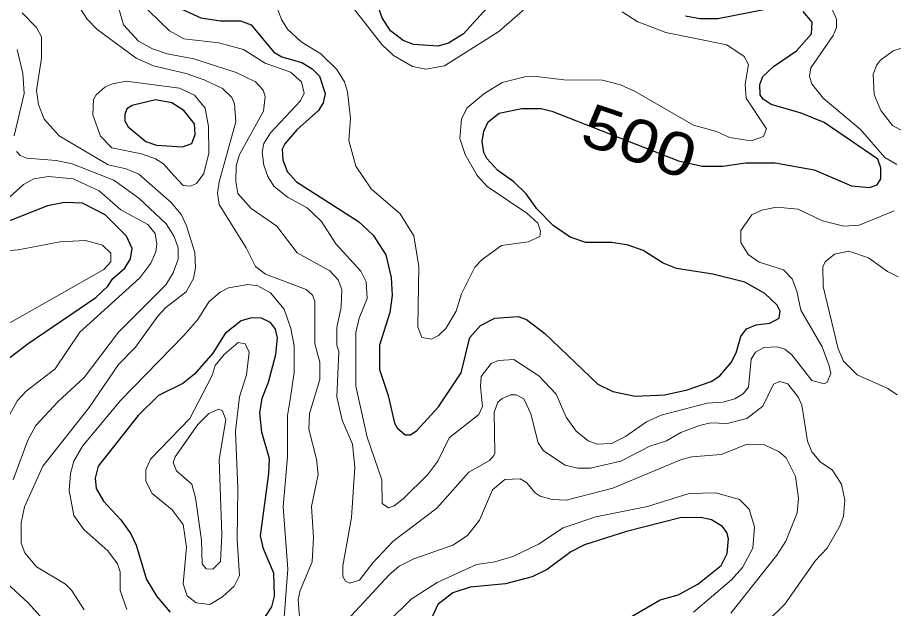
# Model space of a CAD drawing. Extents: x 577 to 602.9, y 7483.8 to 7511.6.
# Drawn here: x 595.926 to 597.557, y 7484.927 to 7486.028 of the extents above; entities that cross this region are included whole.
import ezdxf
from ezdxf.enums import TextEntityAlignment as Align

# ---------------------------------------------------------------- set-up
doc = ezdxf.new("R2010")
doc.units = 0
doc.header["$LTSCALE"] = 0.032
doc.layers.add('1', color=7, linetype='Continuous', lineweight=25)
doc.layers.add('2', color=7, linetype='Continuous', lineweight=13)
doc.layers.add('61', color=7, linetype='Continuous')

msp = doc.modelspace()

# ---------------------------------------------------------------- linework, layer by layer
at = {"layer": '1'}
for points in [[(596.8685, 7486.1208), (596.7564, 7485.9975), (596.7286, 7485.98), (596.7095, 7485.9745), (596.6634, 7485.9776), (596.6443, 7485.9848), (596.6204, 7486.0031), (596.6053, 7486.0269), (596.5703, 7486.1263)], [(596.2324, 7486.0436), (596.2674, 7486.0269), (596.3039, 7486.0214), (596.3413, 7486.0214), (596.3612, 7486.0142), (596.4033, 7485.9633), (596.4185, 7485.9546), (596.4558, 7485.9442), (596.4749, 7485.9323), (596.4884, 7485.9188), (596.4988, 7485.8862), (596.4956, 7485.8687), (596.4868, 7485.8544), (596.4463, 7485.8186), (596.424, 7485.7924), (596.4192, 7485.7828), (596.42, 7485.7629), (596.428, 7485.7407), (596.4455, 7485.7216), (596.5608, 7485.6476), (596.5886, 7485.6222), (596.6117, 7485.5856), (596.622, 7485.5435), (596.6236, 7485.5101), (596.6196, 7485.4783), (596.6005, 7485.4178), (596.6005, 7485.3725), (596.6165, 7485.324), (596.6284, 7485.2723), (596.6332, 7485.2636), (596.6483, 7485.2508), (596.6578, 7485.2508), (596.6697, 7485.2588), (596.7103, 7485.3025), (596.7524, 7485.3662), (596.7683, 7485.4321), (596.7882, 7485.4544), (596.8152, 7485.4679), (596.8582, 7485.4711), (596.8741, 7485.4655), (596.9083, 7485.4393), (597.0069, 7485.3447), (597.0347, 7485.3312), (597.0761, 7485.3224)], [(597.0761, 7485.3224), (597.1317, 7485.3248), (597.1731, 7485.3343), (597.2176, 7485.3502), (597.2343, 7485.3606), (597.255, 7485.3852), (597.2645, 7485.4035), (597.2733, 7485.4337), (597.2836, 7485.4481), (597.3019, 7485.4552), (597.3273, 7485.4584), (597.3448, 7485.4679), (597.3464, 7485.4807), (597.3409, 7485.4918), (597.3178, 7485.5141), (597.2804, 7485.5347), (597.2208, 7485.5498), (597.1532, 7485.5602), (597.1285, 7485.5705), (597.0912, 7485.5936), (597.0633, 7485.6039), (597.0331, 7485.6087), (596.9846, 7485.6087), (596.9552, 7485.619), (596.9234, 7485.6405), (596.8932, 7485.6715), (596.8733, 7485.6993), (596.8502, 7485.7216), (596.8208, 7485.7431), (596.8001, 7485.7653), (596.7946, 7485.7765), (596.7914, 7485.7971), (596.7946, 7485.8162), (596.8025, 7485.8337), (596.8232, 7485.8496), (596.8653, 7485.8584), (596.9011, 7485.8584), (596.921, 7485.8536), (597.1572, 7485.7606), (597.2009, 7485.751), (597.2399, 7485.751), (597.282, 7485.7574), (597.3369, 7485.7574), (597.41, 7485.7439), (597.4792, 7485.7144), (597.5126, 7485.7113), (597.5269, 7485.716), (597.5341, 7485.7272), (597.5341, 7485.7478), (597.5285, 7485.7637), (597.4283, 7485.8321), (597.3854, 7485.8496), (597.3297, 7485.8655), (597.3146, 7485.8759), (597.3091, 7485.8838), (597.3083, 7485.9029), (597.3138, 7485.918), (597.3337, 7485.9363), (597.3766, 7485.9657), (597.4045, 7485.9975), (597.4061, 7486.019), (597.3894, 7486.0389)], [(597.3417, 7486.0468), (597.2303, 7486.0254), (597.1969, 7486.0254), (597.1699, 7486.0301)], [(595.904, 7485.3884), (595.9461, 7485.421), (596.0718, 7485.5061), (596.094, 7485.5276), (596.1036, 7485.5419), (596.1258, 7485.561), (596.1362, 7485.5785), (596.1393, 7485.5975), (596.129, 7485.6206), (596.0893, 7485.6604), (596.0471, 7485.6818), (596.0137, 7485.6834), (595.9819, 7485.6771), (595.9016, 7485.6453)], [(596.3866, 7484.9105), (596.3994, 7484.9304), (596.4049, 7484.9503), (596.4033, 7484.9932), (596.3843, 7485.0385), (596.3787, 7485.0624), (596.394, 7485.1784), (596.3953, 7485.2062), (596.3811, 7485.2556), (596.3771, 7485.2914), (596.3819, 7485.3192), (596.3938, 7485.3487), (596.4073, 7485.4003), (596.4105, 7485.4314), (596.4065, 7485.4473), (596.397, 7485.46), (596.3803, 7485.4679), (596.362, 7485.4687), (596.3429, 7485.4632), (596.3127, 7485.4393), (596.2896, 7485.4027), (596.2554, 7485.3638), (596.234, 7485.3463), (596.1886, 7485.324), (596.1505, 7485.2866), (596.0765, 7485.192), (596.071, 7485.1697), (596.0726, 7485.1507), (596.0861, 7485.1268), (596.1187, 7485.0926), (596.137, 7485.0664), (596.1473, 7485.0449), (596.1664, 7484.9813), (596.1855, 7484.9495), (596.2101, 7484.9201)], [(597.0172, 7484.8819), (597.123, 7484.9431), (597.1564, 7484.9527), (597.193, 7484.9725), (597.2367, 7485.0075), (597.2478, 7485.0298), (597.2502, 7485.0568), (597.247, 7485.0688), (597.2391, 7485.0799), (597.2184, 7485.0926), (597.1985, 7485.0966), (597.1604, 7485.0958), (597.0602, 7485.0703), (596.9822, 7485.0457), (596.9568, 7485.033), (596.9123, 7484.9996), (596.8844, 7484.9861), (596.8351, 7484.9733), (596.7691, 7484.967), (596.7365, 7484.9566), (596.7087, 7484.9344), (596.688, 7484.889)]]:
    msp.add_lwpolyline(points, dxfattribs=at)
msp.add_lwpolyline([(596.2356, 7485.8544), (596.2133, 7485.8687), (596.1831, 7485.8743), (596.1393, 7485.8639), (596.1298, 7485.8576), (596.1258, 7485.8472), (596.1258, 7485.8353), (596.1322, 7485.8242), (596.1648, 7485.7971), (596.1847, 7485.79), (596.2332, 7485.7868), (596.2507, 7485.7932), (596.257, 7485.8099), (596.2554, 7485.8297)], close=True, dxfattribs=at)
at = {"layer": '2'}
for points in [[(596.5401, 7486.0603), (596.6045, 7485.9776), (596.626, 7485.957), (596.6618, 7485.9363), (596.6864, 7485.9315), (596.7214, 7485.9379), (596.8224, 7486.0015), (596.9202, 7486.0874)], [(597.5635, 7485.7542), (597.5412, 7485.7669), (597.4959, 7485.8194), (597.4267, 7485.8774), (597.4053, 7485.9045), (597.4013, 7485.918), (597.4037, 7485.9339), (597.445, 7485.9943), (597.4514, 7486.0094), (597.4514, 7486.0246), (597.4418, 7486.046), (597.4259, 7486.0675), (597.4124, 7486.0794), (597.383, 7486.089), (597.3377, 7486.0882), (597.2327, 7486.0731), (597.2009, 7486.0731), (597.1635, 7486.0794)], [(596.1075, 7486.0715), (596.1234, 7486.0142), (596.1513, 7485.984), (596.1775, 7485.9697), (596.2046, 7485.9601), (596.2546, 7485.9506), (596.3334, 7485.9252), (596.3692, 7485.9077), (596.3835, 7485.8926), (596.3874, 7485.8806), (596.3843, 7485.8536), (596.3397, 7485.7725), (596.3334, 7485.7518), (596.3326, 7485.7224), (596.3366, 7485.7001), (596.3612, 7485.6723), (596.4089, 7485.6389), (596.4471, 7485.5896), (596.5075, 7485.5562), (596.5234, 7485.5395), (596.5298, 7485.5212), (596.529, 7485.4886), (596.521, 7485.4504), (596.521, 7485.4178), (596.5242, 7485.4059), (596.521, 7485.3216), (596.5306, 7485.2779), (596.5497, 7485.2334), (596.5544, 7485.1904), (596.5481, 7485.0966), (596.5322, 7485.0067), (596.5322, 7484.9869), (596.5369, 7484.9781), (596.5449, 7484.9741), (596.5632, 7484.9797), (596.5878, 7485.0123), (596.6252, 7485.0521)], [(596.1521, 7486.058), (596.2093, 7486.0031), (596.2356, 7485.988), (596.3008, 7485.9808), (596.3469, 7485.9681), (596.3874, 7485.9427), (596.4344, 7485.926), (596.455, 7485.9077), (596.4598, 7485.887), (596.4534, 7485.8727), (596.397, 7485.813), (596.3851, 7485.7932)], [(596.0503, 7484.9248), (596.0264, 7484.9614), (596.0153, 7484.9725), (595.9612, 7485.0051), (595.9398, 7485.0306), (595.9326, 7485.0489), (595.9326, 7485.087), (595.939, 7485.1165), (595.9732, 7485.192), (596.0598, 7485.3017), (596.1139, 7485.3813), (596.1457, 7485.4139), (596.1871, 7485.4719), (596.2022, 7485.4878), (596.2403, 7485.5172), (596.2539, 7485.5419), (596.2578, 7485.5618), (596.2562, 7485.5904), (596.2411, 7485.6397), (596.2316, 7485.6604), (596.2125, 7485.6834), (596.1521, 7485.7359), (596.1282, 7485.7462), (596.0948, 7485.7534), (596.0034, 7485.8075), (595.9755, 7485.8385), (595.9652, 7485.8655), (595.9612, 7485.8918), (595.9708, 7485.9522), (595.9708, 7485.992), (595.9612, 7486.0094), (595.935, 7486.0365)], [(596.0423, 7486.046), (596.0559, 7486.0246), (596.0741, 7486.0063), (596.1473, 7485.9522), (596.1791, 7485.9379), (596.2403, 7485.9236), (596.2737, 7485.9116), (596.3079, 7485.8957), (596.3254, 7485.879), (596.3302, 7485.8671), (596.3326, 7485.8337), (596.3016, 7485.7216), (596.2984, 7485.7009), (596.3016, 7485.6794), (596.3517, 7485.5991), (596.3692, 7485.5641), (596.3882, 7485.5498), (596.4638, 7485.5212), (596.4757, 7485.5109), (596.4797, 7485.4997), (596.4797, 7485.4202), (596.4892, 7485.386), (596.4892, 7485.3534), (596.4701, 7485.2906), (596.4685, 7485.2612), (596.4829, 7485.2055), (596.486, 7485.1769), (596.4733, 7485.1173), (596.4773, 7485.0592), (596.4749, 7485.0139), (596.4526, 7484.9606), (596.4487, 7484.9431), (596.4526, 7484.8954)], [(596.5409, 7485.8894), (596.5353, 7485.9077), (596.521, 7485.9307), (596.4908, 7485.9601), (596.4542, 7485.9824), (596.4288, 7486.0063), (596.4177, 7486.0238), (596.4081, 7486.0492)], [(597.0522, 7486.0381), (597.08, 7486.0206), (597.1333, 7485.9999), (597.247, 7485.9768), (597.2796, 7485.9554), (597.2876, 7485.9403), (597.2812, 7485.9037), (597.2828, 7485.8774), (597.321, 7485.8202), (597.3154, 7485.8059), (597.2924, 7485.7979), (597.2518, 7485.8043), (597.2279, 7485.8154), (597.185, 7485.8274), (597.0761, 7485.8902), (597.049, 7485.9021), (597.0156, 7485.9108), (596.9433, 7485.9116), (596.8924, 7485.918), (596.8709, 7485.9172), (596.8288, 7485.9069), (596.7946, 7485.8854), (596.7628, 7485.8592), (596.7532, 7485.8385), (596.75, 7485.8027), (596.7596, 7485.7725), (596.7818, 7485.7335), (596.8009, 7485.7128), (596.8749, 7485.6635), (596.8948, 7485.6445), (596.9003, 7485.6301), (596.8987, 7485.6198), (596.8773, 7485.6103), (596.8272, 7485.6031), (596.7914, 7485.5769), (596.7779, 7485.5626), (596.7532, 7485.5133), (596.7429, 7485.4807), (596.7238, 7485.4488), (596.7103, 7485.4353), (596.6968, 7485.429), (596.6793, 7485.4321), (596.6713, 7485.452), (596.6737, 7485.5641), (596.6642, 7485.6214), (596.6387, 7485.662), (596.5846, 7485.7089), (596.556, 7485.751), (596.5433, 7485.7987), (596.5465, 7485.8401), (596.5409, 7485.8894)], [(597.5802, 7485.9729), (597.5571, 7485.9657), (597.5333, 7485.9482), (597.5261, 7485.9395), (597.5198, 7485.922), (597.5214, 7485.8846), (597.5341, 7485.8544), (597.5556, 7485.8266), (597.5818, 7485.8122)], [(595.9199, 7485.8075), (595.9382, 7485.8862), (595.9358, 7485.9236), (595.9254, 7485.9681)], [(596.3851, 7485.7932), (596.3819, 7485.7773), (596.3851, 7485.7526), (596.3922, 7485.7319), (596.4033, 7485.7136), (596.4288, 7485.693), (596.4654, 7485.6731), (596.4924, 7485.6476), (596.5186, 7485.6063), (596.5656, 7485.5554), (596.5751, 7485.5355), (596.5775, 7485.5045), (596.5624, 7485.4679), (596.556, 7485.4409), (596.556, 7485.3415), (596.5775, 7485.2461), (596.6045, 7485.1666), (596.6053, 7485.1228), (596.6172, 7485.1149), (596.6276, 7485.1181), (596.6443, 7485.1316), (596.6904, 7485.1769), (596.7087, 7485.2015), (596.7302, 7485.2453), (596.785, 7485.2882), (596.7922, 7485.3033), (596.7882, 7485.3407), (596.7898, 7485.359), (596.8081, 7485.3836), (596.8216, 7485.3892), (596.8502, 7485.3908), (596.8971, 7485.3606), (596.929, 7485.3264), (596.948, 7485.2835), (596.9663, 7485.2572), (596.9886, 7485.2397), (597.0053, 7485.2334), (597.0323, 7485.2342), (597.0586, 7485.2477), (597.0975, 7485.2747), (597.1246, 7485.2874), (597.2104, 7485.3097), (597.2399, 7485.3113), (597.2621, 7485.3176), (597.2772, 7485.3272), (597.2876, 7485.3391), (597.2924, 7485.3916), (597.3003, 7485.4043), (597.3162, 7485.4131), (597.3409, 7485.4147), (597.3552, 7485.4099), (597.3679, 7485.3995), (597.4053, 7485.3518), (597.4283, 7485.3455), (597.4339, 7485.3487), (597.441, 7485.3646), (597.4379, 7485.3789), (597.4244, 7485.4147), (597.3846, 7485.483), (597.3774, 7485.518), (597.3687, 7485.5411), (597.3528, 7485.5578), (597.3075, 7485.5721), (597.2868, 7485.5864), (597.2733, 7485.6087), (597.2733, 7485.6309), (597.2939, 7485.6604), (597.3122, 7485.6691), (597.3393, 7485.6747), (597.3798, 7485.6707), (597.4251, 7485.6492), (597.4649, 7485.6389), (597.4935, 7485.6413), (597.5587, 7485.6675)], [(595.9183, 7485.1666), (595.9453, 7485.2405), (595.9604, 7485.2683), (596.0018, 7485.3129), (596.0503, 7485.3574), (596.1139, 7485.4417), (596.2022, 7485.53), (596.2157, 7485.5522), (596.2252, 7485.5777), (596.2252, 7485.5991), (596.2181, 7485.6198), (596.203, 7485.6437), (596.1521, 7485.6914), (596.1052, 7485.7248), (596.028, 7485.755), (595.9978, 7485.7614), (595.9437, 7485.7661), (595.931, 7485.7709), (595.9239, 7485.7781)], [(595.861, 7485.1984), (595.9262, 7485.3145), (595.9421, 7485.332), (595.9962, 7485.3733), (596.0423, 7485.4417), (596.1537, 7485.5427), (596.1743, 7485.5705), (596.1839, 7485.5912), (596.1855, 7485.6055), (596.1823, 7485.6254), (596.1688, 7485.6421), (596.1187, 7485.6699), (596.0781, 7485.7049), (596.0296, 7485.7272), (595.9835, 7485.7319), (595.9565, 7485.7272), (595.9374, 7485.7168), (595.8968, 7485.6802)], [(595.8594, 7485.5896), (595.927, 7485.5952), (596.0058, 7485.6103), (596.0527, 7485.6127), (596.0845, 7485.6039), (596.0996, 7485.5888), (596.0996, 7485.5729), (596.0869, 7485.5586), (595.9119, 7485.4592)], [(597.5659, 7485.5451), (597.546, 7485.5546), (597.511, 7485.5801), (597.4744, 7485.5928), (597.4474, 7485.5872), (597.4299, 7485.5729), (597.4259, 7485.5634), (597.4267, 7485.5268), (597.4546, 7485.4107), (597.4641, 7485.3876), (597.4896, 7485.3622), (597.5468, 7485.3367), (597.5643, 7485.3248)], [(596.1298, 7484.9256), (596.1171, 7484.9606), (596.1171, 7484.9956), (596.1123, 7485.0107), (596.094, 7485.0346), (596.0495, 7485.0743), (596.0312, 7485.1006), (596.0225, 7485.1467), (596.0248, 7485.1785), (596.0312, 7485.2015), (596.0471, 7485.2294), (596.1179, 7485.3145), (596.2356, 7485.4353), (596.2618, 7485.4655), (596.2825, 7485.4981), (596.3032, 7485.5164), (596.3191, 7485.5244), (596.3548, 7485.5308), (596.3739, 7485.5284), (596.397, 7485.5148), (596.4224, 7485.4846), (596.4352, 7485.4488), (596.4415, 7485.4162), (596.4415, 7485.3669), (596.4344, 7485.32), (596.4288, 7485.2866), (596.4288, 7485.2095), (596.4208, 7485.1165), (596.4296, 7485.0004), (596.4208, 7484.8867)], [(596.6252, 7485.0521), (596.7071, 7485.1141), (596.7667, 7485.1809), (596.8049, 7485.2031), (596.8129, 7485.2119), (596.8152, 7485.2167), (596.8137, 7485.2922), (596.8208, 7485.3113), (596.8288, 7485.3184), (596.8447, 7485.3248), (596.855, 7485.3248), (596.8693, 7485.3176), (596.882, 7485.2898), (596.8956, 7485.2357), (596.9059, 7485.2206), (596.9457, 7485.1944), (596.9695, 7485.1888), (596.9934, 7485.1888), (597.0498, 7485.2015), (597.1039, 7485.2294), (597.1349, 7485.2397), (597.1611, 7485.2548), (597.1961, 7485.2683), (597.2168, 7485.2731), (597.2478, 7485.2715), (597.2844, 7485.2811), (597.3138, 7485.3041), (597.3337, 7485.3447), (597.3456, 7485.3502), (597.3607, 7485.3455), (597.3806, 7485.32), (597.387, 7485.3057), (597.3973, 7485.2389), (597.4053, 7485.219), (597.4212, 7485.2), (597.4434, 7485.1856), (597.4609, 7485.1586), (597.4665, 7485.1292), (597.4641, 7485.099), (597.4577, 7485.0807), (597.4339, 7485.0393), (597.4124, 7485.0163), (597.3552, 7484.9352), (597.2892, 7484.8708)], [(596.8995, 7485.1363), (596.9218, 7485.13), (596.948, 7485.1292), (597.0347, 7485.1515), (597.1627, 7485.2047), (597.1818, 7485.2095), (597.2367, 7485.2143), (597.2852, 7485.2334), (597.317, 7485.2318), (597.3448, 7485.219), (597.3576, 7485.2079), (597.3751, 7485.1729), (597.3806, 7485.1324), (597.3782, 7485.1053), (597.3568, 7485.0529), (597.3401, 7485.0266), (597.2542, 7484.9185)], [(596.5163, 7484.8803), (596.618, 7484.99), (596.6371, 7485.0059), (596.6642, 7485.0195), (596.7365, 7485.0449), (596.7644, 7485.0632), (596.7866, 7485.0918), (596.8105, 7485.1483), (596.8335, 7485.1674), (596.8622, 7485.1689), (596.8741, 7485.1618), (596.89, 7485.1427), (596.8995, 7485.1363)], [(597.185, 7484.9201), (597.2558, 7484.9805), (597.2764, 7485.0035), (597.2955, 7485.0393), (597.2987, 7485.0791), (597.2884, 7485.1125), (597.2709, 7485.13), (597.2264, 7485.1427), (597.1771, 7485.1411), (597.0991, 7485.1173), (597.0029, 7485.0982), (596.9425, 7485.0775), (596.8964, 7485.0473), (596.8486, 7485.0242), (596.8152, 7485.0139), (596.7811, 7485.0091), (596.7079, 7484.9757), (596.6594, 7484.9447), (596.6165, 7484.9026)], [(596.1712, 7484.5813), (596.2093, 7484.5821), (596.2483, 7484.5749), (596.2594, 7484.5781), (596.2713, 7484.5885), (596.2713, 7484.6052), (596.2459, 7484.6839), (596.2236, 7484.7825), (596.2173, 7484.7944), (596.203, 7484.8048), (596.1075, 7484.8246), (596.0726, 7484.8485), (596.0288, 7484.866), (596.0042, 7484.8803), (595.9787, 7484.901), (595.9461, 7484.9376), (595.8817, 7484.9964)]]:
    msp.add_lwpolyline(points, dxfattribs=at)
for points in [[(596.2173, 7485.7335), (596.2348, 7485.7152), (596.2483, 7485.7136), (596.2594, 7485.7184), (596.2729, 7485.7375), (596.2825, 7485.7749), (596.2817, 7485.825), (596.2753, 7485.8592), (596.2554, 7485.883), (596.2276, 7485.8965), (596.1282, 7485.9093), (596.1028, 7485.9045), (596.0885, 7485.8981), (596.0726, 7485.8838), (596.0678, 7485.8751), (596.0662, 7485.8464), (596.0805, 7485.8067), (596.102, 7485.7852), (596.1568, 7485.7741), (596.1831, 7485.7645), (596.1982, 7485.755)], [(596.3111, 7485.4003), (596.3373, 7485.4226), (596.3501, 7485.4202), (596.3572, 7485.4043), (596.3525, 7485.3622), (596.3397, 7485.3216), (596.3318, 7485.2572), (596.3366, 7485.1515), (596.335, 7485.0552), (596.3397, 7484.9884), (596.3294, 7484.9686), (596.3079, 7484.9487), (596.2841, 7484.9344), (596.2586, 7484.9376), (596.2419, 7484.9511), (596.2348, 7484.9733), (596.2411, 7485.0417), (596.2348, 7485.0839), (596.2141, 7485.1109), (596.1767, 7485.1411), (596.1648, 7485.1642), (596.1648, 7485.1856), (596.1735, 7485.2055), (596.2467, 7485.2811), (596.2888, 7485.3614), (596.2944, 7485.3797)], [(596.2578, 7485.1332), (596.269, 7485.0544), (596.2698, 7485.0107), (596.2777, 7485.0012), (596.2896, 7485.0004), (596.3039, 7485.0147), (596.3063, 7485.0648), (596.3016, 7485.2047), (596.3143, 7485.2787), (596.3079, 7485.2954), (596.3008, 7485.2986), (596.2825, 7485.2906), (596.2618, 7485.2699), (596.2197, 7485.2095), (596.2157, 7485.1992), (596.222, 7485.1833), (596.2507, 7485.1586)]]:
    msp.add_lwpolyline(points, close=True, dxfattribs=at)

# ---------------------------------------------------------------- texts
at = {"layer": '61', "width": 1.2}
msp.add_text('500', height=0.08, rotation=341.304, dxfattribs=at).set_placement((597.0716, 7485.7596), align=Align.CENTER)

doc.saveas('drawing.dxf')
